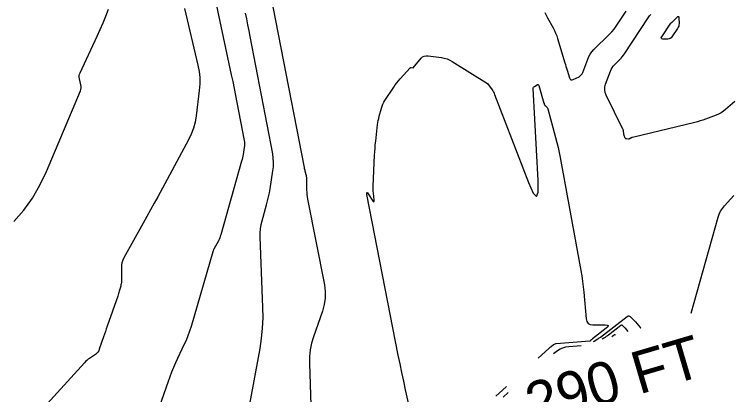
# Model space of a CAD drawing. Extents: x 1768942 to 1774819, y 723037 to 732099.
# Drawn here: x 1770546.4 to 1770648.3, y 726606.2 to 726660.1 of the extents above; entities that cross this region are included whole.
import ezdxf

# ---------------------------------------------------------------- set-up
doc = ezdxf.new("R2010")
doc.units = 0
doc.layers.add('R_Contour Annot', color=7, linetype='Continuous')
doc.layers.add('R_Contours', color=7, linetype='Continuous')

msp = doc.modelspace()

# ---------------------------------------------------------------- linework, layer by layer
at = {"layer": 'R_Contours'}
for points in [[(1770582.31, 726664.83), (1770587.44, 726638.4), (1770587.46, 726638.27), (1770587.49, 726638.14), (1770587.52, 726638.01), (1770587.56, 726637.89), (1770587.7, 726637.38), (1770587.73, 726637.26), (1770587.75, 726637.13), (1770587.76, 726637), (1770587.77, 726636.87), (1770587.79, 726635.19), (1770587.8, 726634.87), (1770587.83, 726634.55), (1770587.87, 726634.23), (1770587.92, 726633.91), (1770590.31, 726621.78), (1770590.43, 726620.84), (1770590.43, 726619.9), (1770590.29, 726618.98), (1770590.04, 726618.06), (1770588.75, 726614.41), (1770588.47, 726613.49), (1770588.28, 726612.56), (1770588.18, 726611.61), (1770588.18, 726610.65), (1770588.41, 726604.75)], [(1770574.36, 726664.44), (1770577.12, 726651.52), (1770577.32, 726650.54), (1770577.52, 726649.56), (1770577.72, 726648.58), (1770577.91, 726647.6), (1770578.94, 726642.2), (1770578.98, 726641.95), (1770578.99, 726641.71), (1770578.98, 726641.46), (1770578.95, 726641.22), (1770578.8, 726640.23), (1770578.76, 726639.98), (1770578.71, 726639.74), (1770578.65, 726639.5), (1770578.58, 726639.26), (1770575.63, 726628.87), (1770575.56, 726628.65), (1770575.48, 726628.43), (1770575.38, 726628.21), (1770575.28, 726628), (1770574.63, 726626.82), (1770574.61, 726626.79), (1770574.6, 726626.76), (1770574.59, 726626.73), (1770574.58, 726626.69), (1770574.54, 726626.56), (1770574.53, 726626.53), (1770574.52, 726626.5), (1770574.51, 726626.47), (1770574.5, 726626.43), (1770571.41, 726615.88), (1770571.2, 726615.21), (1770570.96, 726614.55), (1770570.7, 726613.89), (1770570.41, 726613.25), (1770569.22, 726610.7), (1770568.93, 726610.06), (1770568.66, 726609.42), (1770568.4, 726608.76), (1770568.16, 726608.1), (1770566.9, 726604.45)], [(1770546.31, 726630.72), (1770547.69, 726632.33), (1770548.92, 726634.05), (1770549.99, 726635.87), (1770550.91, 726637.8), (1770555.74, 726649.23), (1770555.81, 726649.44), (1770555.85, 726649.65), (1770555.85, 726649.87), (1770555.81, 726650.09), (1770555.6, 726650.96), (1770555.57, 726651.18), (1770555.57, 726651.39), (1770555.61, 726651.6), (1770555.69, 726651.81), (1770558.12, 726656.99), (1770558.55, 726657.93), (1770558.96, 726658.88), (1770559.34, 726659.83), (1770559.7, 726660.79)], [(1770570.46, 726660.92), (1770572.37, 726652.89), (1770572.54, 726652), (1770572.64, 726651.11), (1770572.65, 726650.21), (1770572.58, 726649.31), (1770572.14, 726645.7), (1770571.98, 726644.81), (1770571.75, 726643.94), (1770571.44, 726643.11), (1770571.05, 726642.29), (1770566.68, 726634.24), (1770566.17, 726633.31), (1770565.66, 726632.37), (1770565.15, 726631.44), (1770564.63, 726630.51), (1770561.9, 726625.58), (1770561.74, 726625.24), (1770561.62, 726624.9), (1770561.56, 726624.54), (1770561.53, 726624.17), (1770561.54, 726622.29), (1770561.54, 726622.11), (1770561.52, 726621.93), (1770561.48, 726621.75), (1770561.44, 726621.58), (1770561.23, 726620.88), (1770561.18, 726620.7), (1770561.12, 726620.53), (1770561.06, 726620.36), (1770561.01, 726620.18), (1770559.53, 726615.9), (1770559.4, 726615.53), (1770559.27, 726615.16), (1770559.14, 726614.79), (1770559.02, 726614.42), (1770558.41, 726612.66), (1770558.32, 726612.44), (1770558.19, 726612.24), (1770558.04, 726612.07), (1770557.85, 726611.92), (1770557.04, 726611.36), (1770556.84, 726611.22), (1770556.65, 726611.07), (1770556.47, 726610.9), (1770556.3, 726610.72), (1770549.56, 726603.29)], [(1770579.74, 726604.88), (1770581.19, 726612.74), (1770581.41, 726614.19), (1770581.55, 726615.64), (1770581.62, 726617.1), (1770581.6, 726618.57), (1770581.2, 726628.56), (1770581.2, 726629.14), (1770581.25, 726629.72), (1770581.34, 726630.29), (1770581.48, 726630.85), (1770582.12, 726633.1), (1770582.27, 726633.66), (1770582.4, 726634.23), (1770582.52, 726634.8), (1770582.62, 726635.37), (1770583.02, 726637.89), (1770583.09, 726638.5), (1770583.1, 726639.11), (1770583.07, 726639.72), (1770582.98, 726640.33), (1770579.81, 726656.93), (1770579.64, 726657.76), (1770579.48, 726658.59), (1770579.31, 726659.42), (1770579.14, 726660.24)], [(1770621.57, 726660.34), (1770621.74, 726659.96), (1770621.93, 726659.6), (1770622.73, 726658.15), (1770622.92, 726657.79), (1770623.09, 726657.42), (1770623.24, 726657.03), (1770623.37, 726656.64), (1770624.4, 726653.22), (1770624.47, 726652.96), (1770624.55, 726652.7), (1770624.63, 726652.45), (1770624.71, 726652.19), (1770625.06, 726651.08), (1770625.14, 726650.9), (1770625.26, 726650.8), (1770625.41, 726650.79), (1770625.59, 726650.84), (1770626.4, 726651.24), (1770626.58, 726651.35), (1770626.73, 726651.49), (1770626.86, 726651.66), (1770626.95, 726651.85), (1770627.65, 726653.73), (1770627.81, 726654.11), (1770628, 726654.45), (1770628.24, 726654.78), (1770628.51, 726655.08), (1770630.69, 726657.24), (1770631.04, 726657.61), (1770631.37, 726657.99), (1770631.68, 726658.39), (1770631.97, 726658.8), (1770633.09, 726660.5)], [(1770648.49, 726647.72), (1770647.17, 726646.58), (1770646.86, 726646.34), (1770646.53, 726646.12), (1770646.18, 726645.94), (1770645.82, 726645.78), (1770644.32, 726645.23), (1770643.95, 726645.09), (1770643.57, 726644.97), (1770643.19, 726644.86), (1770642.8, 726644.76), (1770633.98, 726642.65), (1770633.93, 726642.63), (1770633.88, 726642.61), (1770633.83, 726642.59), (1770633.79, 726642.57), (1770633.61, 726642.46), (1770633.57, 726642.43), (1770633.52, 726642.42), (1770633.47, 726642.41), (1770633.42, 726642.41), (1770633.14, 726642.43), (1770633.08, 726642.44), (1770633.03, 726642.46), (1770632.99, 726642.5), (1770632.96, 726642.55), (1770632.82, 726642.9), (1770632.79, 726642.97), (1770632.77, 726643.05), (1770632.75, 726643.13), (1770632.74, 726643.2), (1770632.7, 726643.52), (1770632.69, 726643.6), (1770632.67, 726643.67), (1770632.65, 726643.75), (1770632.62, 726643.82), (1770630.24, 726648.64), (1770630.1, 726649.02), (1770630.04, 726649.4), (1770630.06, 726649.79), (1770630.16, 726650.18), (1770630.85, 726652.04), (1770630.95, 726652.28), (1770631.08, 726652.51), (1770631.24, 726652.72), (1770631.41, 726652.92), (1770632.17, 726653.67), (1770632.36, 726653.86), (1770632.53, 726654.07), (1770632.7, 726654.28), (1770632.85, 726654.5), (1770636.2, 726659.59), (1770636.38, 726659.84), (1770636.58, 726660.06)], [(1770603.36, 726600.06), (1770601.82, 726606.88), (1770601.55, 726608.11), (1770601.29, 726609.34), (1770601.04, 726610.57), (1770600.79, 726611.8), (1770596.34, 726634.56), (1770596.31, 726634.76), (1770596.33, 726634.84), (1770596.4, 726634.8), (1770596.52, 726634.64), (1770597.12, 726633.73), (1770597.24, 726633.58), (1770597.31, 726633.54), (1770597.35, 726633.62), (1770597.35, 726633.8), (1770597.26, 726634.77), (1770597.24, 726635.01), (1770597.23, 726635.26), (1770597.23, 726635.5), (1770597.24, 726635.74), (1770597.43, 726640.11), (1770597.45, 726640.6), (1770597.49, 726641.1), (1770597.53, 726641.59), (1770597.58, 726642.09), (1770597.86, 726644.45), (1770597.9, 726644.75), (1770597.95, 726645.05), (1770598.01, 726645.34), (1770598.09, 726645.63), (1770598.4, 726646.79), (1770598.49, 726647.08), (1770598.6, 726647.35), (1770598.74, 726647.62), (1770598.89, 726647.87), (1770600.15, 726649.77), (1770600.36, 726650.07), (1770600.57, 726650.37), (1770600.8, 726650.65), (1770601.05, 726650.93), (1770602.47, 726652.48), (1770602.5, 726652.51), (1770602.54, 726652.53), (1770602.58, 726652.54), (1770602.62, 726652.54), (1770602.89, 726652.52), (1770604.03, 726653.85), (1770604.24, 726654.04), (1770604.47, 726654.16), (1770604.72, 726654.22), (1770605, 726654.22), (1770606.9, 726653.95), (1770607.31, 726653.87), (1770607.7, 726653.76), (1770608.08, 726653.6), (1770608.44, 726653.4), (1770613.45, 726650.3), (1770614.09, 726649.38), (1770614.19, 726649.23), (1770614.28, 726649.06), (1770614.36, 726648.9), (1770614.43, 726648.73), (1770619.23, 726636.25), (1770619.91, 726634.73), (1770620.36, 726634.27), (1770620.59, 726634.87), (1770620.59, 726636.54), (1770619.9, 726649.55), (1770619.91, 726649.65), (1770619.94, 726649.74), (1770619.99, 726649.81), (1770620.07, 726649.87), (1770620.45, 726650.09), (1770620.53, 726650.12), (1770620.6, 726650.12), (1770620.65, 726650.07), (1770620.69, 726649.99), (1770621.43, 726647.51), (1770621.44, 726647.48), (1770621.45, 726647.44), (1770621.46, 726647.41), (1770621.47, 726647.38), (1770621.52, 726647.25), (1770621.53, 726647.22), (1770621.54, 726647.19), (1770621.56, 726647.16), (1770621.59, 726647.14), (1770621.85, 726646.91), (1770621.89, 726646.86), (1770621.93, 726646.8), (1770621.96, 726646.74), (1770621.99, 726646.68), (1770623.09, 726642.62), (1770623.28, 726641.91), (1770623.44, 726641.21), (1770623.6, 726640.5), (1770623.73, 726639.79), (1770626.65, 726623.79), (1770626.78, 726623.02), (1770626.89, 726622.26), (1770626.99, 726621.49), (1770627.07, 726620.72), (1770627.42, 726616.95), (1770627.51, 726616.57), (1770627.69, 726616.31), (1770627.98, 726616.15), (1770628.36, 726616.1), (1770630.09, 726616.11), (1770630.41, 726616.08), (1770630.55, 726615.99), (1770630.5, 726615.83), (1770630.26, 726615.61), (1770628.31, 726614.11), (1770628.28, 726614.09), (1770628.26, 726614.07), (1770628.23, 726614.05), (1770628.2, 726614.03), (1770628.05, 726613.94), (1770628.04, 726613.93), (1770628.04, 726613.92), (1770628.03, 726613.91), (1770628.03, 726613.9), (1770628.02, 726613.85), (1770628.02, 726613.84), (1770628.01, 726613.84), (1770628.01, 726613.83), (1770628, 726613.83), (1770627.97, 726613.81), (1770627.96, 726613.81), (1770627.95, 726613.81), (1770627.94, 726613.8), (1770627.93, 726613.8), (1770623.17, 726613.41), (1770623.07, 726613.39), (1770622.97, 726613.36), (1770622.88, 726613.32), (1770622.79, 726613.26), (1770622.44, 726613.01), (1770622.36, 726612.95), (1770622.27, 726612.88), (1770622.19, 726612.81), (1770622.11, 726612.74), (1770620.61, 726611.39)], [(1770642.28, 726617.77), (1770646.13, 726631.35), (1770646.28, 726631.78), (1770646.47, 726632.2), (1770646.72, 726632.58), (1770647.01, 726632.94), (1770648.36, 726634.44)], [(1770628.46, 726613.7), (1770628.46, 726613.7), (1770628.48, 726613.74), (1770628.5, 726613.77), (1770628.53, 726613.79), (1770629.06, 726614.12), (1770629.16, 726614.18), (1770629.26, 726614.25), (1770629.35, 726614.31), (1770629.45, 726614.38), (1770633.25, 726617.3), (1770633.35, 726617.37), (1770633.46, 726617.38), (1770633.56, 726617.35), (1770633.66, 726617.28), (1770634.05, 726616.91), (1770634.14, 726616.82), (1770634.24, 726616.72), (1770634.33, 726616.62), (1770634.42, 726616.52), (1770635.13, 726615.7), (1770635.16, 726615.67)], [(1770633.37, 726615.15), (1770632.97, 726615.61), (1770632.92, 726615.66), (1770632.87, 726615.71), (1770632.82, 726615.77), (1770632.77, 726615.81), (1770632.56, 726616.01), (1770632.51, 726616.05), (1770632.46, 726616.06), (1770632.41, 726616.05), (1770632.35, 726616.02), (1770630.58, 726614.66), (1770630.42, 726614.54), (1770630.26, 726614.43), (1770630.09, 726614.31), (1770629.92, 726614.2), (1770629.69, 726614.07)], [(1770631.07, 726614.47), (1770631.21, 726614.56), (1770631.24, 726614.58), (1770631.26, 726614.59), (1770631.29, 726614.61), (1770631.32, 726614.63), (1770631.45, 726614.74), (1770631.46, 726614.74), (1770631.46, 726614.74), (1770631.47, 726614.74), (1770631.47, 726614.74), (1770631.49, 726614.72), (1770631.5, 726614.71), (1770631.51, 726614.7), (1770631.55, 726614.65), (1770631.56, 726614.64), (1770631.57, 726614.63), (1770631.58, 726614.63), (1770631.59, 726614.62)], [(1770622.79, 726612.03), (1770623.37, 726612.45), (1770623.73, 726612.69), (1770624.11, 726612.86), (1770624.52, 726612.98), (1770624.94, 726613.04), (1770626.73, 726613.19)], [(1770616.12, 726607.35), (1770615.56, 726606.85), (1770614.6, 726605.99)], [(1770615.67, 726605.88), (1770616.37, 726606.5)]]:
    msp.add_lwpolyline(points, dxfattribs=at)
msp.add_lwpolyline([(1770639.42, 726658.83), (1770639.43, 726658.85), (1770639.45, 726658.87), (1770639.47, 726658.89), (1770639.55, 726658.94), (1770639.57, 726658.96), (1770639.59, 726658.98), (1770639.61, 726658.99), (1770639.63, 726659.01), (1770640.3, 726659.69), (1770640.4, 726659.77), (1770640.48, 726659.78), (1770640.53, 726659.72), (1770640.55, 726659.59), (1770640.58, 726658.78), (1770640.57, 726658.6), (1770640.53, 726658.42), (1770640.47, 726658.25), (1770640.38, 726658.09), (1770639.56, 726656.88), (1770639.45, 726656.75), (1770639.32, 726656.66), (1770639.17, 726656.6), (1770639, 726656.58), (1770638.29, 726656.58), (1770638.14, 726656.59), (1770638.07, 726656.65), (1770638.06, 726656.74), (1770638.12, 726656.87), (1770639.4, 726658.81)], close=True, dxfattribs=at)

# ---------------------------------------------------------------- texts
at = {"layer": 'R_Contour Annot'}
msp.add_text('290 FT', height=6, rotation=16.4133, dxfattribs=at).set_placement((1770619.94, 726601.81))

doc.saveas('drawing.dxf')
